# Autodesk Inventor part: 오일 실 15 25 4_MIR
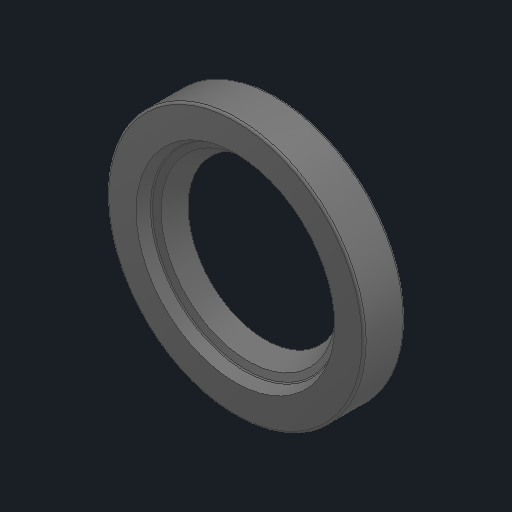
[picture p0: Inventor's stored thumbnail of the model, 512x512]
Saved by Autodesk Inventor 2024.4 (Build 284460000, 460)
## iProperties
Created: 2025-10
Part Number: 오일 실 15 25 4_MIR
Material: 고무
Description: 오일 실 - 비스프링, 조립 GA
Document SubType Name: Modeling
Designer: user
Density: 0.93 g/cm^3
Appearance: 기본값
Author: jhkim
Sending System: Autodesk Inventor 2026
Preprocessor: ST-DEVELOPER v20.1
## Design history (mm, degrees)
derived "오일 실 15 25 4.ipt"
feature "솔리드1::오일 실 15 25 4.ipt" dims "d0" = 10
tag "피쳐 태그1"
node "솔리드1"
